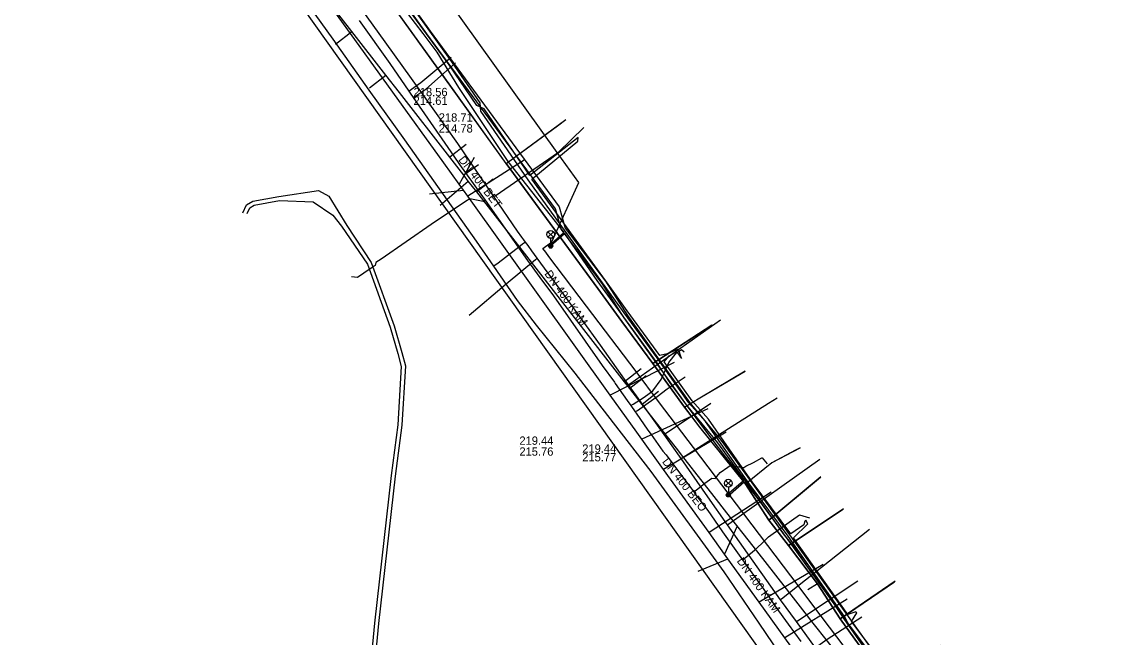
# Model space of a CAD drawing. Extents: x -595540 to -593988, y -1160850 to -1159202.
# Drawn here: x -595319.4 to -595213.2, y -1160524 to -1160464.7 of the extents above; entities that cross this region are included whole.
import ezdxf

# ---------------------------------------------------------------- set-up
doc = ezdxf.new("R2010")
doc.units = 0
for name, color, linetype in [('BKOM-ODVODNENI_trasa sítě', 7, 'Continuous'), ('BVK-JEDNOTNA_popisy', 7, 'Continuous'), ('BVK-JEDNOTNA_trasa sítě', 7, 'Continuous'), ('BVK-KANALIZACE_ vyřazená trasa sítě', 7, 'Continuous'), ('BVK-KANALIZACE_popisy zrušené sítě', 7, 'Continuous'), ('BVK-VODOVOD_trasa sítě', 7, 'Continuous'), ('BVK-VODOVOD_trasa zrušené sítě', 7, 'Continuous'), ('CETIN_kabel podzemní', 7, 'Continuous'), ('DESTOVA_trasa neprovozované sítě', 7, 'Continuous'), ('DSP-SDEL-VODAFONE_kabel', 7, 'Continuous'), ('EON-NN_kabel', 7, 'Continuous'), ('EON-VN_kabel', 7, 'Continuous'), ('INNOGY-STL_trasa sítě', 7, 'Continuous'), ('JEDNOTNA_trasa neprovozované sítě', 7, 'Continuous'), ('TSB_kabel VO', 7, 'Continuous'), ('TSB_lampy VO', 7, 'Continuous')]:
    doc.layers.add(name, color=color, linetype=linetype)

msp = doc.modelspace()

# ---------------------------------------------------------------- linework, layer by layer
at = {"layer": 'BKOM-ODVODNENI_trasa sítě'}
for points in [[(-595275.89, -1160477.77), (-595277.32, -1160480.36)], [(-595280.17, -1160481.28), (-595276.91, -1160480.93)], [(-595250.58, -1160513.33), (-595251.77, -1160515.98)], [(-595254.3, -1160517.6), (-595251.45, -1160516.42)]]:
    msp.add_lwpolyline(points, dxfattribs=at)
at = {"layer": 'BVK-JEDNOTNA_popisy'}
for p, q in [((-595279.285, -1160474.454), (-595279.285, -1160474.454)), ((-595271.521, -1160505.563), (-595271.521, -1160505.563))]:
    msp.add_line(p, q, dxfattribs=at)
at = {"layer": 'BVK-JEDNOTNA_trasa sítě'}
for points in [[(-595278.8, -1160478.3), (-595288.613, -1160464.682), (-595298.833, -1160450.5), (-595300.356, -1160448.387), (-595300.859, -1160447.689), (-595302.464, -1160445.461), (-595305.875, -1160440.728), (-595306.946, -1160439.242)], [(-595260.22, -1160504.23), (-595262.784, -1160500.652), (-595276.492, -1160481.521), (-595276.914, -1160480.933), (-595277.323, -1160480.362), (-595278.8, -1160478.3)], [(-595230.25, -1160545.89), (-595231.282, -1160544.457), (-595231.731, -1160543.831), (-595236.049, -1160537.829), (-595237.969, -1160535.16), (-595241.287, -1160530.548), (-595245.985, -1160524.017), (-595248.45, -1160520.59), (-595251.45, -1160516.42), (-595251.768, -1160515.979), (-595253.266, -1160513.897), (-595257.646, -1160507.808), (-595259.73, -1160504.91), (-595260.22, -1160504.23)]]:
    msp.add_lwpolyline(points, dxfattribs=at)
at = {"layer": 'BVK-KANALIZACE_ vyřazená trasa sítě'}
for p, q in [((-595289.231, -1160466.88), (-595287.654, -1160465.65)), ((-595285.959, -1160471.075), (-595284.382, -1160469.845)), ((-595276.646, -1160476.521), (-595278.224, -1160477.75)), ((-595275.46, -1160478.48), (-595276.867, -1160479.494)), ((-595279.14, -1160482.38), (-595276.437, -1160480.047)), ((-595274.048, -1160479.859), (-595275.626, -1160481.088)), ((-595259.815, -1160498.142), (-595261.393, -1160499.371)), ((-595259.311, -1160498.789), (-595260.889, -1160500.018)), ((-595258.119, -1160500.32), (-595259.697, -1160501.549))]:
    msp.add_line(p, q, dxfattribs=at)
for points in [[(-595283.06, -1160471.54), (-595284.382, -1160469.845), (-595287.654, -1160465.65), (-595307.58, -1160440.1)], [(-595258.536, -1160503.04), (-595259.697, -1160501.549), (-595260.889, -1160500.018), (-595261.393, -1160499.371), (-595275.626, -1160481.088), (-595276.437, -1160480.047), (-595276.867, -1160479.494), (-595278.224, -1160477.751), (-595283.06, -1160471.54)], [(-595233.912, -1160534.539), (-595234.503, -1160533.782), (-595237.417, -1160530.055), (-595238.162, -1160529.102), (-595238.316, -1160528.905), (-595241.869, -1160524.359), (-595243.23, -1160522.618), (-595244.006, -1160521.625), (-595245.823, -1160519.301), (-595247.868, -1160516.686), (-595249.026, -1160515.205), (-595251.545, -1160511.982), (-595252.764, -1160510.423), (-595253.695, -1160509.233), (-595255.912, -1160506.397), (-595256.281, -1160505.924), (-595257.131, -1160504.837), (-595258.536, -1160503.04)]]:
    msp.add_lwpolyline(points, dxfattribs=at)
at = {"layer": 'BVK-KANALIZACE_popisy zrušené sítě'}
for p, q in [((-595281.705, -1160471.082), (-595281.705, -1160471.082)), ((-595265.473, -1160505.402), (-595265.473, -1160505.402))]:
    msp.add_line(p, q, dxfattribs=at)
at = {"layer": 'BVK-VODOVOD_trasa sítě'}
for p, q in [((-595271.1, -1160485.7), (-595271.3, -1160485.44)), ((-595270.93, -1160485.92), (-595271.22, -1160486.14)), ((-595270.93, -1160485.92), (-595271.1, -1160485.7)), ((-595270.69, -1160486.25), (-595270.93, -1160485.92)), ((-595273.56, -1160487.94), (-595273.98, -1160488.26))]:
    msp.add_line(p, q, dxfattribs=at)
for points in [[(-595273.98, -1160488.26), (-595275.64, -1160485.83), (-595282.54, -1160476.07), (-595285.98, -1160471.31), (-595289.45, -1160466.4), (-595292.92, -1160461.56), (-595296.39, -1160456.7), (-595299.81, -1160451.78), (-595303.24, -1160446.83), (-595306.71, -1160441.98), (-595310.13, -1160437.14), (-595313.63, -1160432.31), (-595317.11, -1160427.51), (-595320.57, -1160422.61), (-595323.95, -1160417.9), (-595327.48, -1160412.92), (-595328.53, -1160410.62), (-595328.79, -1160410.05)], [(-595271.3, -1160485.44), (-595271.71, -1160484.89), (-595273.99, -1160481.54), (-595277.44, -1160476.43), (-595281.02, -1160471.42), (-595284.43, -1160466.65), (-595287.32, -1160462.6)], [(-595273.99, -1160481.54), (-595273.87, -1160481.46), (-595267.77, -1160477.26), (-595265.33, -1160474.88)], [(-595271.22, -1160486.14), (-595271.58, -1160486.41), (-595271.88, -1160486.65), (-595273.56, -1160487.94)], [(-595267.23, -1160490.96), (-595269.8, -1160487.49), (-595270.31, -1160486.78), (-595270.69, -1160486.25)], [(-595269.8, -1160487.49), (-595269.98, -1160487.62), (-595272.78, -1160489.974), (-595276.36, -1160492.98)], [(-595220.87, -1160558.73), (-595221.32, -1160558.15), (-595223.17, -1160555.82), (-595227.03, -1160551.3), (-595230.95, -1160546.74), (-595232.86, -1160544.52), (-595234.7, -1160542.18), (-595238.33, -1160537.35), (-595241.81, -1160532.49), (-595245.07, -1160527.57), (-595248.44, -1160522.6), (-595251.82, -1160517.68), (-595258.83, -1160508.01), (-595262.46, -1160503.34), (-595266.15, -1160498.56), (-595269.86, -1160493.93), (-595271.69, -1160491.54), (-595273.98, -1160488.26)], [(-595243.02, -1160525), (-595244.86, -1160522.46), (-595246.39, -1160520.35), (-595249.95, -1160515.32), (-595251.49, -1160513.14), (-595253.39, -1160510.45), (-595255.95, -1160506.77), (-595256.81, -1160505.53), (-595257.6, -1160504.44), (-595260.26, -1160500.74), (-595261.02, -1160499.68), (-595263.72, -1160495.86), (-595267.23, -1160490.96)], [(-595261.02, -1160499.68), (-595260.88, -1160499.58), (-595252.17, -1160493.41)], [(-595257.6, -1160504.44), (-595257.47, -1160504.36), (-595253.08, -1160501.43)], [(-595255.95, -1160506.77), (-595255.85, -1160506.7), (-595247.56, -1160501.44), (-595246.71, -1160500.92)], [(-595251.49, -1160513.14), (-595251.37, -1160513.06), (-595242.59, -1160506.83)], [(-595246.39, -1160520.35), (-595246.29, -1160520.27), (-595237.83, -1160513.55)], [(-595244.86, -1160522.46), (-595244.76, -1160522.4), (-595238.94, -1160518.53)]]:
    msp.add_lwpolyline(points, dxfattribs=at)
at = {"layer": 'BVK-VODOVOD_trasa zrušené sítě'}
for points in [[(-595268.675, -1160487.322), (-595268.988, -1160486.907), (-595269.262, -1160486.546), (-595268.388, -1160485.892), (-595265.8, -1160480.181), (-595267.875, -1160477.288), (-595281.437, -1160458.383), (-595288.694, -1160448.267), (-595292.619, -1160442.796), (-595297.63, -1160435.81), (-595299.919, -1160432.62), (-595310.873, -1160417.35), (-595318.612, -1160406.561), (-595321.415, -1160402.654), (-595322.498, -1160401.145), (-595327.972, -1160400.775), (-595328.204, -1160400.881)], [(-595237.224, -1160540.826), (-595237.678, -1160540.24), (-595323.624, -1160419.463), (-595323.813, -1160419.04), (-595328.79, -1160410.05)], [(-595231.512, -1160536.403), (-595233.407, -1160533.9), (-595237.25, -1160528.824), (-595243.174, -1160521.018), (-595244.591, -1160519.129), (-595249.924, -1160512.085), (-595254.751, -1160505.71), (-595256.39, -1160503.546), (-595258.118, -1160501.264), (-595260.289, -1160498.397), (-595265.058, -1160492.099), (-595268.675, -1160487.322)]]:
    msp.add_lwpolyline(points, dxfattribs=at)
at = {"layer": 'CETIN_kabel podzemní'}
for points in [[(-595272.78, -1160478.37), (-595278.13, -1160470.92), (-595285.3, -1160460.93)], [(-595267.86, -1160474.74), (-595267.06, -1160474.14)], [(-595272.78, -1160478.37), (-595267.86, -1160474.74)], [(-595272.78, -1160478.37), (-595263.97, -1160490.4), (-595261.67, -1160493.57), (-595258.68, -1160497.62)], [(-595253.01, -1160493.92), (-595258.68, -1160497.62)], [(-595258.68, -1160497.62), (-595255.62, -1160501.82)], [(-595255.62, -1160501.82), (-595254.16, -1160500.91), (-595249.8, -1160498.34)], [(-595255.62, -1160501.82), (-595254.15, -1160503.76), (-595249.75, -1160509.23)], [(-595244.944, -1160505.964), (-595247.23, -1160507.17), (-595249.75, -1160509.23)], [(-595244.5, -1160505.73), (-595244.944, -1160505.964)], [(-595249.75, -1160509.23), (-595247.51, -1160512.69)], [(-595242.52, -1160508.53), (-595247.51, -1160512.69)], [(-595240.34, -1160511.61), (-595245.63, -1160515.14)], [(-595247.51, -1160512.69), (-595245.63, -1160515.14)], [(-595245.63, -1160515.14), (-595242.84, -1160518.84)], [(-595235.34, -1160518.58), (-595240.64, -1160522.19)], [(-595242.84, -1160518.84), (-595243.77, -1160519.4)], [(-595242.84, -1160518.84), (-595240.64, -1160522.19)], [(-595240.64, -1160522.19), (-595235.9, -1160528.76)]]:
    msp.add_lwpolyline(points, dxfattribs=at)
at = {"layer": 'DESTOVA_trasa neprovozované sítě'}
for p, q in [((-595275.89, -1160477.77), (-595277.323, -1160480.362)), ((-595280.17, -1160481.28), (-595276.914, -1160480.933)), ((-595250.58, -1160513.33), (-595251.768, -1160515.979)), ((-595254.3, -1160517.6), (-595251.45, -1160516.42))]:
    msp.add_line(p, q, dxfattribs=at)
at = {"layer": 'DSP-SDEL-VODAFONE_kabel'}
for p, q in [((-595272.78, -1160478.372), (-595267.059, -1160474.137)), ((-595261.67, -1160493.566), (-595263.966, -1160490.403)), ((-595258.679, -1160497.621), (-595252.947, -1160493.882)), ((-595254.149, -1160503.758), (-595255.619, -1160501.823)), ((-595249.793, -1160509.161), (-595254.149, -1160503.758)), ((-595247.511, -1160512.688), (-595242.552, -1160508.556)), ((-595245.632, -1160515.137), (-595240.366, -1160511.629)), ((-595240.638, -1160522.188), (-595235.427, -1160518.641)), ((-595242.842, -1160518.837), (-595243.767, -1160519.403))]:
    msp.add_line(p, q, dxfattribs=at)
for points in [[(-595263.966, -1160490.403), (-595272.78, -1160478.372), (-595278.126, -1160470.915), (-595287.258, -1160458.2), (-595288.716, -1160456.115), (-595293.613, -1160449.293), (-595298.519, -1160442.368), (-595292.804, -1160438.28)], [(-595235.899, -1160528.761), (-595240.638, -1160522.188), (-595242.842, -1160518.837), (-595245.632, -1160515.137), (-595247.511, -1160512.688), (-595249.793, -1160509.161), (-595254.149, -1160503.758), (-595255.619, -1160501.823), (-595258.679, -1160497.621), (-595261.67, -1160493.566), (-595263.966, -1160490.403), (-595272.78, -1160478.372), (-595287.258, -1160458.2)], [(-595255.619, -1160501.823), (-595258.679, -1160497.621), (-595261.67, -1160493.566)], [(-595255.619, -1160501.823), (-595254.164, -1160500.91), (-595249.776, -1160498.322)], [(-595244.543, -1160505.754), (-595247.229, -1160507.166), (-595249.764, -1160509.236)], [(-595230.926, -1160524.754), (-595235.899, -1160528.761), (-595240.638, -1160522.188), (-595242.842, -1160518.837), (-595245.632, -1160515.137), (-595247.511, -1160512.688), (-595249.793, -1160509.161)]]:
    msp.add_lwpolyline(points, dxfattribs=at)
at = {"layer": 'EON-NN_kabel'}
for points in [[(-595235.393, -1160527.991), (-595239.548, -1160522.459), (-595239.051, -1160521.62), (-595239.131, -1160521.521), (-595239.912, -1160521.79), (-595245.133, -1160514.411), (-595243.771, -1160513.057), (-595243.953, -1160512.709), (-595244.057, -1160512.79), (-595244.151, -1160513.143), (-595245.385, -1160514.027), (-595249.104, -1160509.005), (-595253.315, -1160502.964), (-595254.891, -1160501.216), (-595257.576, -1160497.463), (-595257.112, -1160496.885), (-595256.385, -1160496.5), (-595256.313, -1160496.585), (-595255.925, -1160497.135), (-595256.214, -1160496.245), (-595257.283, -1160496.694), (-595257.997, -1160496.858), (-595261.138, -1160492.551), (-595262.991, -1160489.987), (-595270.316, -1160479.869), (-595265.913, -1160476.218), (-595265.852, -1160475.872), (-595265.867, -1160475.853), (-595270.516, -1160479.513), (-595274.903, -1160473.108), (-595275.262, -1160472.939), (-595275.608, -1160472.775), (-595278.284, -1160468.863), (-595289.183, -1160453.926)], [(-595235.696, -1160528.179), (-595239.874, -1160522.652), (-595240.242, -1160521.982), (-595245.662, -1160514.243), (-595249.368, -1160509.218), (-595253.607, -1160503.199), (-595255.219, -1160501.394), (-595258.26, -1160497.055), (-595261.428, -1160492.747), (-595270.679, -1160479.944), (-595275.231, -1160473.311), (-595275.262, -1160472.939), (-595275.295, -1160472.536), (-595278.01, -1160468.572), (-595288.676, -1160453.68)], [(-595298.143, -1160483.116), (-595297.781, -1160482.327), (-595297.18, -1160482), (-595294.674, -1160481.533), (-595290.872, -1160480.968), (-595289.859, -1160481.518), (-595288.136, -1160484.319), (-595285.789, -1160487.88), (-595283.574, -1160493.998), (-595282.844, -1160496.549), (-595282.499, -1160497.847), (-595282.838, -1160503.563), (-595283.465, -1160508.455), (-595285.086, -1160522.659), (-595285.686, -1160529.056), (-595286.171, -1160539.546), (-595286.083, -1160539.916), (-595284.968, -1160540.135)], [(-595297.725, -1160483.163), (-595297.473, -1160482.615), (-595297.044, -1160482.382), (-595294.626, -1160481.931), (-595291.378, -1160482.044), (-595289.472, -1160483.327), (-595288.633, -1160484.388), (-595286.149, -1160488.062), (-595283.954, -1160494.122), (-595283.23, -1160496.655), (-595282.903, -1160497.887), (-595283.236, -1160503.525), (-595283.863, -1160508.407), (-595285.484, -1160522.617), (-595286.086, -1160529.028), (-595286.615, -1160539.468), (-595286.408, -1160540.265), (-595285.022, -1160540.531)]]:
    msp.add_lwpolyline(points, dxfattribs=at)
at = {"layer": 'EON-VN_kabel'}
for points in [[(-595213.236, -1160556.754), (-595220.594, -1160547.971), (-595224.883, -1160542.711), (-595231.938, -1160533.557), (-595234.229, -1160530.496), (-595245.151, -1160515.279), (-595252.434, -1160505.242), (-595255.446, -1160501.602), (-595261.426, -1160493.221), (-595263.552, -1160489.92), (-595267.509, -1160484.697), (-595268.044, -1160482.73), (-595280.437, -1160465.869), (-595293.222, -1160447.996)], [(-595288.769, -1160453.537), (-595280.123, -1160465.624), (-595267.708, -1160482.518), (-595267.13, -1160484.573), (-595263.236, -1160489.684), (-595261.109, -1160492.985), (-595255.117, -1160501.385), (-595252.111, -1160505.012), (-595244.841, -1160515.037), (-595233.925, -1160530.241)]]:
    msp.add_lwpolyline(points, dxfattribs=at)
at = {"layer": 'INNOGY-STL_trasa sítě'}
for points in [[(-595286.933, -1160464.59), (-595283.998, -1160468.743), (-595282.155, -1160471.409), (-595282.029, -1160471.591)], [(-595282.155, -1160471.409), (-595281.913, -1160471.219), (-595280.997, -1160470.554), (-595278.074, -1160468.128)], [(-595281.735, -1160472.017), (-595281.495, -1160471.85), (-595280.53, -1160471.211), (-595277.682, -1160468.673)], [(-595282.029, -1160471.591), (-595281.735, -1160472.017), (-595278.415, -1160476.835), (-595277.054, -1160478.773), (-595277.032, -1160478.805), (-595275.485, -1160480.954), (-595275.227, -1160481.312), (-595274.824, -1160481.887), (-595270.753, -1160487.698), (-595269.552, -1160489.327), (-595268.234, -1160491.098), (-595263.545, -1160497.807), (-595262.377, -1160499.427), (-595262.305, -1160499.528), (-595261.142, -1160501.164), (-595260.791, -1160501.664), (-595260.367, -1160502.268), (-595260.287, -1160502.383), (-595259.173, -1160504.032), (-595258.83, -1160504.445), (-595257.729, -1160506.047), (-595257.388, -1160506.416), (-595256.21, -1160508.004), (-595254.735, -1160509.984), (-595254.588, -1160510.181), (-595253.4, -1160511.76), (-595253.101, -1160512.192), (-595251.97, -1160513.82), (-595250.051, -1160516.506), (-595248.01, -1160519.362), (-595246.854, -1160521.086), (-595245.641, -1160522.722), (-595244.446, -1160524.391)], [(-595274.824, -1160481.887), (-595275.009, -1160482.016), (-595276.282, -1160481.755), (-595276.709, -1160482.019), (-595280.001, -1160484.221), (-595284.815, -1160487.562), (-595285.344, -1160487.893), (-595285.4, -1160488.176), (-595285.597, -1160488.299), (-595286.485, -1160488.905), (-595287.1, -1160489.351), (-595287.692, -1160489.262)], [(-595260.791, -1160501.664), (-595260.583, -1160501.527), (-595259.527, -1160500.844), (-595258.684, -1160500.237), (-595257.869, -1160499.163), (-595257.325, -1160497.943), (-595257.147, -1160497.516), (-595256.407, -1160496.58), (-595255.915, -1160496.273), (-595255.677, -1160496.498)], [(-595260.367, -1160502.268), (-595260.161, -1160502.123), (-595259.136, -1160501.397), (-595258.259, -1160500.776), (-595257.306, -1160500.06), (-595255.571, -1160498.882)], [(-595254.735, -1160509.984), (-595254.346, -1160509.692), (-595253.66, -1160509.144), (-595253.008, -1160508.66), (-595252.669, -1160508.675), (-595252.19, -1160508.112), (-595251.445, -1160507.582), (-595251.243, -1160507.441), (-595249.931, -1160507.626), (-595249.718, -1160507.495), (-595248.98, -1160507.148), (-595248.199, -1160506.695), (-595248.158, -1160506.703), (-595247.677, -1160507.284)], [(-595250.051, -1160516.506), (-595249.622, -1160516.183), (-595248.887, -1160515.57), (-595248.226, -1160514.965), (-595247.551, -1160514.312), (-595246.327, -1160513.445), (-595244.568, -1160512.182), (-595243.612, -1160512.458)], [(-595243.702, -1160525.472), (-595243.299, -1160525.177), (-595242.573, -1160524.645), (-595241.908, -1160524.159), (-595238.553, -1160521.995)]]:
    msp.add_lwpolyline(points, dxfattribs=at)
at = {"layer": 'JEDNOTNA_trasa neprovozované sítě'}
for p, q in [((-595270.96, -1160477.97), (-595276.492, -1160481.521)), ((-595256.61, -1160497.53), (-595262.784, -1160500.652)), ((-595253.4, -1160501.99), (-595259.73, -1160504.91)), ((-595251.62, -1160504.21), (-595257.646, -1160507.808)), ((-595247.3, -1160510.01), (-595253.266, -1160513.897)), ((-595242.27, -1160516.96), (-595248.45, -1160520.59)), ((-595239.97, -1160520.29), (-595245.985, -1160524.017))]:
    msp.add_line(p, q, dxfattribs=at)
at = {"layer": 'TSB_kabel VO'}
msp.add_lwpolyline([(-595286.72, -1160458.12), (-595280.82, -1160465.84), (-595279.46, -1160467.65), (-595277.39, -1160471.04), (-595272.64, -1160478.18), (-595267.247, -1160485.013), (-595268.487, -1160486.112), (-595268.519, -1160486.292), (-595267.176, -1160485.11), (-595264.06, -1160489.62), (-595258.31, -1160497.53), (-595257.03, -1160499.48), (-595255.47, -1160501.59), (-595253.72, -1160503.97), (-595251.67, -1160506.62), (-595250.36, -1160508.26), (-595249.962, -1160508.898), (-595251.317, -1160510.089), (-595251.415, -1160510.255), (-595251.238, -1160510.18), (-595249.893, -1160508.997), (-595248.7, -1160510.49), (-595247.06, -1160512.7), (-595246.03, -1160514.13), (-595244.54, -1160515.95), (-595243.53, -1160517.33), (-595240.23, -1160522.28), (-595238.27, -1160525.07)], dxfattribs=at)
at = {"layer": 'TSB_lampy VO'}
for p, q in [((-595268.78, -1160485.455), (-595268.25, -1160484.925)), ((-595268.78, -1160484.925), (-595268.25, -1160485.455)), ((-595268.78, -1160485.455), (-595268.25, -1160484.925)), ((-595268.78, -1160484.925), (-595268.25, -1160485.455)), ((-595268.515, -1160485.565), (-595268.515, -1160486.315)), ((-595268.515, -1160485.565), (-595268.515, -1160486.315)), ((-595251.674, -1160509.404), (-595251.144, -1160508.874)), ((-595251.674, -1160508.874), (-595251.144, -1160509.404)), ((-595251.674, -1160509.404), (-595251.144, -1160508.874)), ((-595251.674, -1160508.874), (-595251.144, -1160509.404)), ((-595251.409, -1160509.514), (-595251.409, -1160510.264)), ((-595251.409, -1160509.514), (-595251.409, -1160510.264))]:
    msp.add_line(p, q, dxfattribs=at)
for centre, radius in [((-595268.515, -1160485.19), 0.375), ((-595268.515, -1160485.19), 0.375), ((-595268.515, -1160486.315), 0.2), ((-595268.515, -1160486.315), 0.2), ((-595268.515, -1160486.315), 0.145), ((-595268.515, -1160486.315), 0.145), ((-595268.515, -1160486.315), 0.0876), ((-595268.515, -1160486.315), 0.0876), ((-595251.409, -1160509.139), 0.375), ((-595251.409, -1160509.139), 0.375), ((-595251.409, -1160510.264), 0.2), ((-595251.409, -1160510.264), 0.2), ((-595251.409, -1160510.264), 0.145), ((-595251.409, -1160510.264), 0.145), ((-595251.409, -1160510.264), 0.0876), ((-595251.409, -1160510.264), 0.0876)]:
    msp.add_circle(centre, radius, dxfattribs=at)

# ---------------------------------------------------------------- texts
at = {"layer": 'BVK-JEDNOTNA_popisy'}
for s, p in [('218.71', (-595279.285, -1160474.329)), ('214.78', (-595279.285, -1160475.379)), ('219.44', (-595271.521, -1160505.438)), ('215.76', (-595271.521, -1160506.488))]:
    msp.add_text(s, height=0.8, dxfattribs=at).set_placement(p)
for rotation, p in [(305.5565, (-595269.155, -1160488.984)), (305.69962, (-595250.635, -1160516.637))]:
    msp.add_text('DN 400 KAM', height=0.8, rotation=rotation, dxfattribs=at).set_placement(p)
at = {"layer": 'BVK-KANALIZACE_popisy zrušené sítě'}
for s, p in [('218.56', (-595281.705, -1160471.882)), ('214.61', (-595281.705, -1160472.714)), ('219.44', (-595265.473, -1160506.202)), ('215.77', (-595265.473, -1160507.034))]:
    msp.add_text(s, height=0.8, dxfattribs=at).set_placement(p)
for s, rotation, p in [('DN 400 BET', 307.90752, (-595277.444, -1160478.018)), ('DN 400 BEO', 308.02211, (-595257.824, -1160507.088))]:
    msp.add_text(s, height=0.8, rotation=rotation, dxfattribs=at).set_placement(p)

doc.saveas('drawing.dxf')
